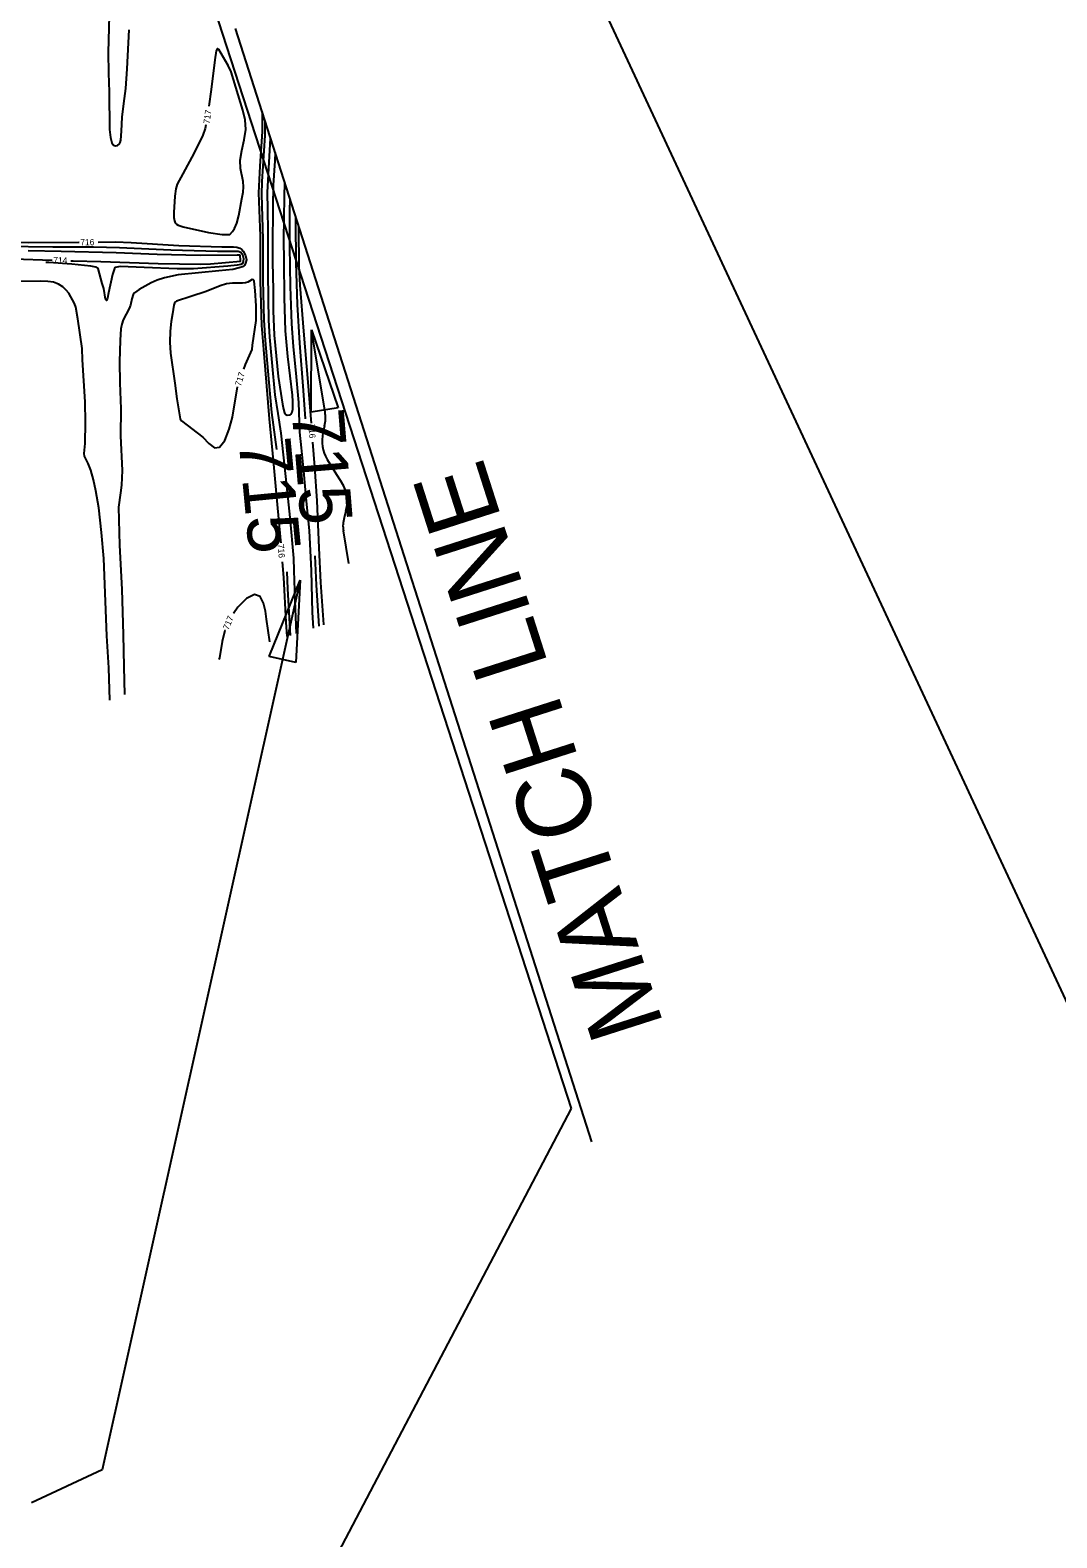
# Model space of a CAD drawing. Extents: x -310467766 to 17062430, y -322263100 to 8322522.
# Drawn here: x 1400655 to 1401306, y 575641 to 576598 of the extents above; entities that cross this region are included whole.
import ezdxf

# ---------------------------------------------------------------- set-up
doc = ezdxf.new("R2010")
doc.units = 0
for name, color, linetype in [('DT_X_Contour_Minor', 7, 'Continuous'), ('DT_X_Terrain_Ground_Line', 7, 'Continuous'), ('Level 19', 7, 'Continuous'), ('Level 31', 7, 'Continuous'), ('Level 40', 7, 'Continuous'), ('SC_Scratch1', 7, 'Continuous'), ('SH_Border', 7, 'Continuous')]:
    doc.layers.add(name, color=color, linetype=linetype)

msp = doc.modelspace()

# ---------------------------------------------------------------- linework, layer by layer
at = {"layer": 'DT_X_Contour_Minor'}
for points in [[(1400704.9, 576606.94), (1400704.38, 576583.51), (1400704.61, 576570.37), (1400704.93, 576558.5), (1400705.23, 576534.71), (1400705.82, 576529.59), (1400706.69, 576526.25), (1400707.73, 576524.79), (1400708.93, 576524.31), (1400710.3, 576524.58), (1400711.58, 576525.6), (1400712.03, 576526.44), (1400712.35, 576527.83), (1400712.72, 576533.63), (1400713.2, 576542.42), (1400714.3, 576551.15), (1400715.5, 576560.59), (1400716.46, 576573.24), (1400717.55, 576597.87)], [(1400766.38, 576537.59), (1400765.92, 576535.3), (1400764.46, 576531.02), (1400758.81, 576519.85), (1400751.6, 576506.56), (1400748.01, 576500.04), (1400747.22, 576496.96), (1400746.63, 576492.33), (1400746.01, 576482.08), (1400746.05, 576478.74), (1400746.34, 576476.69), (1400746.89, 576475.45), (1400747.69, 576474.58), (1400748.77, 576473.92), (1400751.89, 576472.91), (1400768.09, 576469.39), (1400776.57, 576468.04), (1400781.45, 576467.97), (1400783.23, 576469.9), (1400784.53, 576471.94), (1400785.91, 576475.27), (1400787.17, 576480.03), (1400789.21, 576490.66), (1400789.91, 576494.82), (1400790.24, 576498.29), (1400789.99, 576501.66), (1400788.29, 576509.87), (1400788.15, 576515.15), (1400789.19, 576521.33), (1400790.67, 576528.01), (1400791.6, 576534.65), (1400791.23, 576540.87), (1400789.83, 576546.89), (1400782.27, 576571.26), (1400780.45, 576575.17), (1400774.57, 576585.43), (1400773.61, 576586.01), (1400772.88, 576584.48), (1400771.97, 576578.8), (1400769.71, 576560), (1400768.25, 576549.44)], [(1400802, 576545.97), (1400802, 576533.48), (1400800.67, 576511.32), (1400799.81, 576494.54), (1400800.87, 576467.03), (1400800.82, 576456.44), (1400800.79, 576438.47), (1400801.7, 576410.36), (1400802.9, 576395.03), (1400804.04, 576382.19), (1400806.52, 576351.19), (1400809.01, 576324.74), (1400811.4, 576299), (1400813.67, 576274.03), (1400813.8, 576272.43)], [(1400803.84, 576540.22), (1400803.84, 576538.99), (1400803.67, 576530.84), (1400801.9, 576501.64), (1400801.61, 576493.47), (1400802.45, 576465.05), (1400802.43, 576439), (1400803.04, 576413.7), (1400803.89, 576400.78), (1400806.02, 576376.55), (1400807.95, 576355.08), (1400811.05, 576331.71)], [(1400807.22, 576529.66), (1400807.21, 576529.14), (1400805.83, 576506.05), (1400805.25, 576494.81), (1400805.33, 576483.67), (1400805.56, 576470.67), (1400805.61, 576443.63), (1400805.85, 576427.44), (1400806.13, 576413.7), (1400806.73, 576402.9), (1400808.85, 576379.8), (1400810.13, 576366.44), (1400811.95, 576354.57), (1400813.86, 576341.96), (1400816.85, 576314.6), (1400819.6, 576288.43), (1400821.83, 576262.81), (1400822.17, 576254.87), (1400822.8, 576235.83), (1400823.65, 576214.93)], [(1400810.32, 576519.99), (1400810.07, 576514.83), (1400809.1, 576499.32), (1400808.76, 576485.54), (1400808.51, 576460.23), (1400808.71, 576450.61), (1400809.04, 576432.72), (1400809.13, 576419.64), (1400809.65, 576404.18), (1400812.26, 576377.92), (1400814.85, 576360.4), (1400815.53, 576357.18), (1400816.25, 576354.99), (1400817.06, 576353.86), (1400817.93, 576353.51), (1400819.74, 576353.7), (1400820.55, 576354.18), (1400821.14, 576355.3), (1400821.46, 576357.24), (1400821.55, 576362.03), (1400821.29, 576366.22), (1400818.33, 576390.58), (1400816.84, 576406.85), (1400816.22, 576427.98), (1400815.97, 576451.21), (1400815.79, 576464.86), (1400816.17, 576491.98), (1400816.38, 576501.06)], [(1400834.65, 576218.43), (1400834.01, 576228.35), (1400833.27, 576254.73), (1400832.02, 576280.27), (1400830.26, 576298.87), (1400828.43, 576317.9), (1400826.91, 576332.69), (1400826, 576342.71), (1400825.22, 576361.44), (1400823.84, 576377.78), (1400821.83, 576396.99), (1400820.85, 576411.36), (1400819.99, 576435.08), (1400819.61, 576460.34), (1400819.71, 576483.29), (1400819.75, 576490.56)], [(1400829.52, 576351.11), (1400828.28, 576369.02), (1400825.92, 576399.14), (1400824.42, 576423.71), (1400823.55, 576450.16), (1400823.37, 576476.56), (1400823.37, 576479.24)], [(1400186.51, 576470.75), (1400202.94, 576470.71), (1400235.21, 576470.63), (1400266.28, 576469.99), (1400296.63, 576469.21), (1400313.45, 576468.99), (1400346.83, 576469.14), (1400375.84, 576469.04), (1400403.07, 576468.74), (1400429.61, 576468.37), (1400458.3, 576468.46), (1400468.21, 576467.9), (1400496.72, 576465.7), (1400507.81, 576465.12), (1400532.18, 576464.87), (1400558.46, 576464.79), (1400590.86, 576464.9), (1400602.3, 576464.6), (1400635.48, 576463.23), (1400653.71, 576462.97), (1400685.68, 576463.1), (1400685.97, 576463.1)], [(1400833.27, 576348.35), (1400833.08, 576350.77), (1400831.31, 576374.45), (1400828.59, 576406.66), (1400826.15, 576435.85), (1400825.45, 576448.21), (1400825.31, 576471.58), (1400825.31, 576473.2)], [(1400638.09, 576460.64), (1400669.15, 576460.13), (1400694.97, 576460.25), (1400711.46, 576459.82), (1400743.99, 576458.23), (1400773.62, 576457.5), (1400786.85, 576457.5), (1400788.51, 576456.75), (1400789.48, 576455.35), (1400790.18, 576452.93), (1400790.09, 576451.02), (1400789.53, 576449.65), (1400788.6, 576449.1), (1400786.11, 576448.54), (1400780.33, 576447.93), (1400758.53, 576446.31), (1400748.04, 576446.31), (1400727.07, 576447.13), (1400711.97, 576447.68), (1400708.79, 576447.2), (1400708.32, 576446.58), (1400707.09, 576442.59), (1400704.55, 576431.02), (1400703.79, 576427.66), (1400703.16, 576426.12), (1400702.68, 576427.03), (1400701.51, 576433.89), (1400700.48, 576436.99), (1400697.91, 576446.39), (1400696.45, 576447.35), (1400693.37, 576448.01), (1400681.31, 576449.31), (1400666.56, 576450.2), (1400664.85, 576450.22)], [(1400680.69, 576451.42), (1400681.61, 576451.37), (1400682.11, 576451.38), (1400699.56, 576450.83), (1400736.08, 576449.63), (1400763.18, 576449.15), (1400769.25, 576449.46), (1400788.28, 576451.06), (1400788.34, 576451.78), (1400788.06, 576454.79), (1400787.67, 576455.03), (1400786.17, 576455.04), (1400762.64, 576454.83), (1400735.33, 576455.45), (1400709.35, 576456.35), (1400674.49, 576457.33), (1400653.57, 576457.76)], [(1400697.96, 576463.27), (1400708.99, 576463.42), (1400718.84, 576462.99), (1400749.06, 576461.02), (1400776.5, 576460.14), (1400783.8, 576460.21), (1400786.04, 576459.98), (1400787.77, 576459.44), (1400789.06, 576458.6), (1400790.04, 576457.46), (1400791.43, 576454.65), (1400792.12, 576452.04), (1400791.56, 576449.79), (1400790.82, 576448.31), (1400790.18, 576447.79), (1400787.51, 576446.81), (1400783.39, 576445.95), (1400774.56, 576445.03), (1400748.69, 576442.53), (1400740, 576440.47), (1400735.39, 576439.02), (1400731.59, 576437.43), (1400723.99, 576433.15), (1400721.02, 576431.09), (1400720.22, 576430.04), (1400719.41, 576427.33), (1400718.47, 576423.32), (1400717.6, 576421.05), (1400713.8, 576413.92), (1400712.95, 576411.25), (1400712.43, 576408.29), (1400711.91, 576401.11), (1400711.52, 576387.19), (1400711.79, 576373.86), (1400712.31, 576357.48), (1400712.2, 576340.43), (1400713.11, 576318.29), (1400712.87, 576309.13), (1400712.19, 576304.16), (1400710.91, 576295.12), (1400711.57, 576270.94), (1400712.89, 576242.89), (1400713.75, 576214.38), (1400714.2, 576193.75), (1400714.58, 576176.15)], [(1400644.39, 576452.54), (1400668.7, 576451.84)], [(1400705.41, 576172.64), (1400704.83, 576193.1), (1400703.42, 576213.51), (1400702.57, 576235.28), (1400701.46, 576262.49), (1400700.06, 576279.06), (1400698.48, 576294.7), (1400696.58, 576305.5), (1400695.04, 576312.35), (1400693.33, 576318.46), (1400691.63, 576322.78), (1400689.29, 576327.48), (1400689.08, 576329.14), (1400689.66, 576335.5), (1400689.86, 576348.77), (1400689.71, 576361.97), (1400688.07, 576388.46), (1400687.75, 576395.64), (1400684.99, 576414.62), (1400683.79, 576422), (1400682.96, 576424.36), (1400679.31, 576430.79), (1400677.71, 576432.73), (1400675.5, 576434.83), (1400672.78, 576436.62), (1400669.62, 576437.76), (1400665.94, 576438.33), (1400661.62, 576438.5), (1400646.66, 576438.28)], [(1400790.31, 576382.71), (1400791.48, 576385.56), (1400795.8, 576395.03), (1400795.87, 576397.92), (1400798.22, 576413.52), (1400798.18, 576422.72), (1400797.68, 576432.57), (1400796.89, 576438.35), (1400796.41, 576439.4), (1400795.72, 576439.59), (1400793.94, 576438.48), (1400792.9, 576437.83), (1400791.53, 576437.35), (1400789.53, 576437.13), (1400783.25, 576437.17), (1400779.42, 576436.7), (1400775.43, 576435.49), (1400766.6, 576431.88), (1400756.81, 576428.65), (1400747.73, 576425.85), (1400747.07, 576425.29), (1400746.51, 576424.47), (1400746.06, 576423.23), (1400745.04, 576417.81), (1400744.26, 576412.85), (1400743.58, 576406.67), (1400743.39, 576399.81), (1400743.94, 576392.87), (1400746.54, 576373.82), (1400747.97, 576363.86), (1400749.97, 576351.21), (1400750.78, 576349.78), (1400764.29, 576339.44), (1400768.18, 576335.5), (1400771.7, 576332.81), (1400775.03, 576333.1), (1400778.28, 576337.45), (1400781.15, 576344.49), (1400783.23, 576352.18), (1400786.3, 576371.4)], [(1400841.12, 576220.49), (1400841.11, 576220.69), (1400839.21, 576247.27), (1400838.3, 576269.24), (1400837.05, 576299.15), (1400835.42, 576320.6), (1400834.2, 576336.39)], [(1400838.3, 576219.59), (1400836.54, 576245.55), (1400835.73, 576264.14)], [(1400814.76, 576260.46), (1400815.58, 576250.44), (1400817.15, 576222.15), (1400817.64, 576213.01)], [(1400817.67, 576253.97), (1400818.12, 576243.33), (1400819.75, 576213.68)], [(1400806.83, 576209.57), (1400804.89, 576223.99), (1400804.06, 576229.05), (1400802.81, 576234.26), (1400800.69, 576238.32), (1400797.2, 576239.64), (1400792.15, 576237.14), (1400786.53, 576231.63), (1400783.86, 576227.71)], [(1400778.52, 576216.94), (1400778.45, 576216.78), (1400776.73, 576209.78), (1400775.06, 576199.59), (1400774.63, 576198.38)]]:
    msp.add_lwpolyline(points, dxfattribs=at)
at = {"layer": 'DT_X_Terrain_Ground_Line'}
msp.add_line((1401011.33, 575892.47), (1400785.07, 576598.82), dxfattribs=at)
at = {"layer": 'Level 31'}
for p, q in [((1400833.24, 576355.3), (1400833.45, 576407.59)), ((1400841.95, 576355.33), (1400833.45, 576407.59)), ((1400833.45, 576407.59), (1400850.19, 576358.06)), ((1400850.19, 576358.06), (1400833.24, 576355.3)), ((1400841.66, 576346.62), (1400840.64, 576342.3)), ((1400843.39, 576325.42), (1400848.27, 576317.48)), ((1400848.27, 576317.48), (1400852.66, 576310.44)), ((1400855.24, 576292.7), (1400854.02, 576288.22)), ((1400856.95, 576259.44), (1400853.59, 576280.1))]:
    msp.add_line(p, q, dxfattribs=at)
for centre, radius, start, end in [((1400819.85, 576351.73), 22.4, 346.87127, 9.23129), ((1400862.46, 576337.18), 22.4, 166.83244, 211.6763), ((1400833.62, 576298.63), 22.4, 344.69861, 31.80707), ((1400872.54, 576283.19), 19.2, 164.74848, 189.23129)]:
    msp.add_arc(centre, radius, start, end, dxfattribs=at)
at = {"layer": 'Level 40'}
for p, q in [((1400806.57, 576200.33), (1400826.17, 576248.81)), ((1400826.17, 576248.81), (1400823.34, 576196.6)), ((1400823.34, 576196.6), (1400806.57, 576200.33))]:
    msp.add_line(p, q, dxfattribs=at)
msp.add_lwpolyline([(1400826.17, 576248.81), (1400700.58, 575684.39), (1400655.72, 575663.47)], dxfattribs=at)
at = {"layer": 'SC_Scratch1'}
msp.add_lwpolyline([(1392212.45, 573822.06), (1393676.29, 570715.35), (1396857.46, 571041.41), (1399761.19, 572912.69), (1399601.35, 573251.92), (1400998.38, 575913.71), (1400551.67, 577289.29)], close=True, dxfattribs=at)
at = {"layer": 'SH_Border'}
msp.add_line((1402894.39, 572589.21), (1400231.89, 578298.95), dxfattribs=at)

# ---------------------------------------------------------------- texts
at = {"layer": 'DT_X_Terrain_Ground_Line'}
msp.add_text('MATCH LINE', height=46.8, rotation=107.76162, dxfattribs=at).set_placement((1401057.13, 575966.44))
at = {"layer": 'Level 19'}
for s, height, rotation, p in [('717', 4, 82.11058, (1400768.68, 576538.02)), ('716', 4, 0.80214, (1400686.64, 576461.11)), ('714', 4, 358.35072, (1400669.43, 576449.81)), ('717', 4, 71.81453, (1400788.4, 576371.49)), ('715', 33, 274.70461, (1400820.77, 576356.26)), ('716', 4, 274.42959, (1400831.32, 576347.55)), ('715', 33, 275.47811, (1400786.99, 576337.78)), ('716', 4, 274.63013, (1400811.85, 576271.62)), ('717', 4, 67.39702, (1400780.65, 576216.85))]:
    msp.add_text(s, height=height, rotation=rotation, dxfattribs=at).set_placement(p)

doc.saveas('drawing.dxf')
